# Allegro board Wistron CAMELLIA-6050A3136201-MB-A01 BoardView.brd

Outline 288.7 x 124 mm; copper layers: TOP, L2, L3, L4, L5, L6, L7, BOTTOM. Coordinates in mm from the lower left corner of the outline.

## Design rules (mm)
constraint set DEFAULT: min track width 0.102
net group ALS_LOW_LIGHT_EC: nets ALS_LOW_LIGHT_EC ALS_LOW_LIGHT_PCH
net group AUDIO_CBN: nets AUDIO_CBN AUDIO_CBP
net group AUDIO_DMIC_CLK: nets AUDIO_DMIC_CLK UNNAMED_76_CSC0201_I56_A
net group BATLOW#_N: nets BATLOW# BATLOW#_N
net group BT_OFF: nets BT_OFF BT_OFF_R
net group CAMERA_WP#: nets CAMERA_WP# CAMERA_WP#_EC
net group CCG5_I2C_EC_R_INT#: nets CCG5_I2C_EC_INT# CCG5_I2C_EC_R_INT#
net group CCG5_I2C_EC_R_SCL: nets CCG5_I2C_EC_R_SCL CCG5_I2C_EC_SCL
net group CCG5_I2C_EC_R_SDA: nets CCG5_I2C_EC_R_SDA CCG5_I2C_EC_SDA
net group CCG5_PD_ADP_DIS1#: nets CCG5_PD_ADP_DIS1# CCG5_PD_ADP_DIS1#_R
net group CCG5_PD_ADP_DIS2#: nets CCG5_PD_ADP_DIS2# CCG5_PD_ADP_DIS2#_R
net group CFG<0>: nets CFG<0> XDP_CFG<0>
net group CFG<3>: nets CFG<3> XDP_CFG<3>
net group CL_DATA: nets CL_DATA1 CL_RST#1
net group CLICK_PS2_CLK: nets CLICK_PS2_CLK CLICK_PS2_CLK_R
net group CLICKPAD_INT#: nets CLICKPAD_INT# PCH_CLICKPAD_INT#
net group CLK_PCIE0_D: nets CLK_PCIE0_DN CLK_PCIE0_DP
net group CLK_PCIE_XDP_D: nets CLK_PCIE_XDP_DN CLK_PCIE_XDP_DP
net group CLKIN_XTAL: nets CLKIN_XTAL CLKIN_XTAL_R
net group CLKREQ#_WLAN: nets CLKREQ#_WLAN CLKREQ_WLAN_R_N
net group CN1951_PEDET: nets CN1951_PEDET MSATA_DET
net group CNV_BRI_DT: nets CNV_BRI_DT CNV_BRI_DT_R
net group CNV_BRI_RSP: nets CNV_BRI_RSP CNV_BRI_RSP_R
net group CNV_CLKREQ: nets CNV_CLKREQ CNV_CLKREQ_C
net group CNV_RF_RESET#: nets CNV_RF_RESET# RF_RESET#_C
net group CNV_RGI_DT: nets CNV_RGI_DT CNV_RGI_DT_R
net group CNV_RGI_RSP: nets CNV_RGI_RSP CNV_RGI_RSP_R
net group CPU_C10_GATE#: nets CPU_C10_GATE# VCCIO_LP#
net group DDR_PG_CTRL: nets DDR_PG_CTRL DDR_PG_CTRL_R
net group DDR_WR_C_VREF01: nets DDR_WR_C_VREF01 DDR_WR_VREF01
net group DDR_WR_C_VREF02: nets DDR_WR_C_VREF02 DDR_WR_VREF02
net group DMIC_CLK0: nets DMIC_CLK0 DMIC_R_CLK0
net group DMIC_CLK1: nets DMIC_CLK1 DMIC_R_CLK1
net group DMIC_DATA: nets DMIC_DATA0_PP DMIC_DATA1_PP
net group DPWROK: nets DPWROK DSW_PWROK
net group E-DCLK_PCIE3_U4555_CN1300: nets CLK_PCIE3_DN CLK_PCIE3_DP
net group E-DCLK_PCIE5_U4555_U2700: nets CLK_PCIE5_DN CLK_PCIE5_DP
net group E-DMIC0_CN600_MIC600: nets DMIC_CLK0_DB DMIC_DATA0_DB
net group E-PCIE3_U4555_CN1400: nets CLK_PCIE1_DN CLK_PCIE1_DP
net group E-USB2_P1_CN2400: nets USB_P1_DN USB_P1_DP
net group E-USB2_P4_CN3601: nets USB_P3_DN USB_P3_DP
net group E-USB2_P7_CN1300: nets USB_P7_DN USB_P7_DP
net group EC_GPIO67: nets EC_GPIO67 PCH_SLP_S0IX#
net group EMMC_CLK: nets EMMC_CLK EMMC_CLK_IC
net group EMMC_CMD: nets EMMC_CMD EMMC_CMD_IC
net group EMMC_DATA_0: nets EMMC_DATA_0 EMMC_DATA_0_IC
net group EMMC_DATA_1: nets EMMC_DATA_1 EMMC_DATA_1_IC
net group EMMC_DATA_2: nets EMMC_DATA_2 EMMC_DATA_2_IC
net group EMMC_DATA_3: nets EMMC_DATA_3 EMMC_DATA_3_IC
net group EMMC_DATA_4: nets EMMC_DATA_4 EMMC_DATA_4_IC
net group EMMC_DATA_5: nets EMMC_DATA_5 EMMC_DATA_5_IC
net group EMMC_DATA_6: nets EMMC_DATA_6 EMMC_DATA_6_IC
net group EMMC_DATA_7: nets EMMC_DATA_7 EMMC_DATA_7_IC
net group EMMC_RCLK: nets EMMC_RCLK EMMC_RCLK_IC
net group EN_1V05A: nets EN_1V05A VCC_PRIM_PG
net group ESPI_CLK: nets ESPI_CLK LPC_ESPI_CLK
net group ESPI_LPC#: nets ESPI_LPC# TBT_TMU_CLK_OUT
net group EXT_MIC_JACK_DB: nets EXT_MIC_JACK_DB EXT_MIC_JACK_R_DB
net group FAN1_PWM_EC: nets FAN1_PWM FAN1_PWM_EC
net group FAN1_PWM_Q: nets FAN1_PWM_Q FAN1_PWM_Q_R
net group FN_KEY_LED#: nets FN_KEY_LED# FN_KEY_LED#_R
net group H_PECI: nets H_PECI H_PECI_R
net group H_TCK: nets H_TCK JTAGK_TCK
net group H_TDI: nets H_TDI PCH_TDI
net group H_TDO: nets H_TDO PCH_TDO
net group H_TMS: nets H_TMS PCH_TMS
net group H_TRST#: nets H_TRST# XDP_TRST#
net group HDA_BCLK: nets HDA_BCLK HDA_BCLK_PCH
net group HDA_RST#: nets HDA_RST# HDA_RST#_PCH
net group HDA_SDI0: nets HDA_SDI0 HDA_SDI0_R
net group HDA_SDO_R: nets HDA_SDO_Q HDA_SDO_R
net group HDA_SYNC: nets HDA_SYNC HDA_SYNC_PCH
net group HP_VERF_L: nets EXT_MIC_JACK HP_VERF_L
net group ILIM_SEL_PD: nets ILIM_SEL ILIM_SEL_PD
net group INTRUDER#: nets INTRUDER# INTRUDER#_PCH
net group IOT_I2C_EC_SDA: nets IOT_I2C_EC_SDA IOT_I2C_WWAN_SDA
net group IOT_I2C_WWAN_INT#: nets IOT_I2C_EC_INT# IOT_I2C_WWAN_INT#
net group IOT_I2C_WWAN_SCL: nets IOT_I2C_EC_SCL IOT_I2C_WWAN_SCL
net group JD1: nets HPOUT_DET JD1
net group ON_OFF#1: nets ON_OFF#1 SR1#
net group P3V3S_KBL_EN#: nets P3V3S_KBL_EN# P3V3S_KBL_EN#_RC
net group P5V0S_EN#: nets P5V0S_EN# P5V0S_EN#_R
net group PCH_CIO_PLUG_EVENT: nets PCH_CIO_PLUG_EVENT TBT_CIO_PLUG_EVENT
net group PCH_PWROK: nets PCH_PWROK VCCIO_PG
net group PCIE_RCOMPN: nets PCIE_RCOMPN PCIE_RCOMPP
net group PCIE_RX14_D: nets PCIE_RX14_DN PCIE_RX14_DP
net group PCIE_RX16_D: nets PCIE_RX16_DN PCIE_RX16_DP
net group PLAY_MUTE_LED_CNTR: nets PLAY_MUTE_LED_CNTR PLAY_MUTE_LED_CNTR_R
net group PLT_ID2: nets PLT_ID2 PLT_ID2_PCH
net group PM_SLP_A#: nets PM_SLP_A# PM_SLP_A#_COMPARE
net group PP_DETECT#: nets PP_DETECT# PP_DETECT#_R
net group PRC: nets SLP_S3_5R SLP_S5#_3R
net group PRIVACY_LED#: nets PRIVACY_LED# PRIVACY_LED#_R
net group PVCCSTG_EN: nets PVCCSTG_EN VCCPLL_OC_Q_EN
net group PVT_MISO2: nets PVT_MISO2 PVT_MISO2_EC
net group PVT_MISO3: nets PVT_MISO3 PVT_MISO3_EC
net group PVT_MISO_EC: nets PVT_MISO PVT_MISO_EC
net group PVT_MOSI: nets PVT_MOSI PVT_MOSI_EC
net group PVT_SCLK: nets PVT_SCLK PVT_SCLK_EC
net group RBIAS: nets RBIAS RSENSE
net group RECORD_MUTE_LED_CNTRL: nets RECORD_MUTE_LED_CNTRL RECORD_MUTE_LED_CNTRL_R
net group RTD3_CIO_PWR_EN: nets RTD3_CIO_PWR_EN RTD3_CIO_PWR_EN_BUF
net group SCAN_3S_IN: nets SCAN_3S_IN<4> SCAN_3S_IN<7>
net group SCL_BAT_CHG: nets SCL_BAT_CHG SCL_BAT_R_CHG
net group SCL_P: nets SCL_P UNNAMED_20_MP2949GQKLFZ_I283__1
net group SDA_BAT_CHG: nets SDA_BAT_CHG SDA_BAT_R_CHG
net group SDA_P: nets SDA_P UNNAMED_20_MP2949GQKLFZ_I283_SD
net group SDDR_VREF: nets P0V6S_DIMM0_VREF_CA P0V6S_DIMM1_VREF_CA
net group SPI_DATA: nets PCH_SML1DATA SPI_SI_FLH_R
net group SPI_TPM_CS#_R: nets SPI_TPM_CS# SPI_TPM_CS#_R
net group TBT_CLK: nets TBT_EE_CLK TBT_TCK
net group TBT_USB_FORCE_PWR: nets RTD3_USB_PWR_EN TBT_USB_FORCE_PWR
net group TBTA_FO: nets TBTA_FO TBTA_FO_R
net group TBTA_HPD_R: nets PCH_LAN_SMCLK TBTA_HPD_R
net group TBTB_FO: nets TBTB_FO TBTB_FO_R
net group TOUCH_PWR_EN#: nets TOUCH_PWR_EN# TOUCH_PWR_EN#_RC
net group TPM_PLT_RST#_RC: nets TPM_PLT_RST#_RC UNNAMED_65_NMOS2D2SDIODE_I879_3
net group UART: nets UART0_RXD UART0_TXD
net group UIM_CD: nets UIM_CD UIM_CD#
net group UNNAMED_7_CSC0402_I34_A: nets UNNAMED_7_CSC0402_I34_A UNNAMED_7_CSC0402_I43_A
net group UNNAMED_7_CSC0402_I81_B: nets UNNAMED_7_CSC0402_I81_B UNNAMED_7_CSC0402_I84_B
net group UNNAMED_7_LBSS84LT1G_I27_G: nets UNNAMED_7_LBSS84LT1G_I27_G UNNAMED_7_NMOSC_I234_D
net group USB30_RX1_RE_D_DB: nets USB30_RX1_RE_DN_DB USB30_RX1_RE_DP_DB
net group USB30_RX2_RE_D_DB: nets USB30_RX2_RE_DN_DB USB30_RX2_RE_DP_DB
net group USB_P4_D: nets USB_P4_DN USB_P4_DP
net group VCC1_RST#: nets VCC1_R_RST# VCC1_RST#
net group VCCIO_VSSSENSE: nets UNNAMED_18_CSC0402_I59_B VCCIO_VSSSENSE
net group VCCPLL_OC_EN: nets VCCPLL_OC_EN VCCPLL_OC_XDP_EN
net group VCCSA_SENSE: nets VCCSA_VCCSENSE VCCSA_VSSSENSE
net group VCCSENSE: nets VCCSENSE VOSENA
net group VGT_VCCSENSE: nets VGT_VCCSENSE VOSENB
net group VGT_VSSSENSE: nets VGT_VSSSENSE VORTNB
net group VORTNA: nets VORTNA VSSSENSE
net group WWAN_WAKE#_R: nets WWAN_WAKE# WWAN_WAKE#_R
net group XDP_PRSNT#: nets XDP_PRSNT# XDP_PRSNT#_R
net group XTAL24_IN: nets XTAL24_IN XTAL24_OUT
net group XTAL24_IN_PCH: nets XTAL24_IN_PCH XTAL24_OUT_PCH
net group 1V05A_PG: nets 1V05A_PG 5V_PG COMPARE_R_RSMRST_PG COMPARE_RSMRST_PG EC_RSMRST_PG RSMRST_PG
net group 8051_RX_CAPS_LED#: nets 8051_RX_CAPS_LED# CAPS_LED# CAPS_LED#_R
net group 8051_TX_LED_PWRSTBY#: nets 8051_TX_LED_PWRSTBY# LED_PWRSTBY# LED_PWRSTBY#_CNTR LED_PWRSTBY#_CNTR_R
net group ABMON: nets ABMON EC_ADC1 UNNAMED_7_ISL9241HRTZ_I169_29
net group ASY: nets THERMTRIP_CPU#
net group AUDIO-B: nets A_LINEINL A_LINEINR HP_OUT_L1 HP_OUT_R1
net group AUDIO_AVDD1: nets AUDIO_AVDD1 AUDIO_AVDD1_R PCBEEP PCH_SPKR PCH_SPKR_R PCH_SPKR_R_R
net group AUDIO_PDB: nets A_SD# AUDIO_PDB SPKR_EN_AB SPKR_EN_AB_AUDIO
net group BARREL_ADP_DET: nets BARREL_ADP_DET BARREL_ADP_DET_EC UNNAMED_7_PNPA_I117_B UNNAMED_7_RSC0402_I114_B
net group BKLT_EN: nets BKLT_EN EDP_BKLT_EN TOUCH_SWITCH_EN
net group BUF_PLT_RST#: nets BUF_PLT_RST# TD_IREF TD_IREF_R WLAN_PLT_RST#
net group CCG5_MOD_ID1: nets CCG5_MOD_ID1 CCG5_MOD_ID2 CCG5_PVCC_PD CCG5_SWD_CLK CCG5_SWD_XRES CCG5_VBUS_P_CTRL_P1 CCG5_VBUS_P_CTRL_P2
net group CCG5_SBU1_A_DP_DP: nets CCG5_SBU2_A_DN
net group CCG5_SBU1_B_DP_DP: nets CCG5_SBU2_B_DN
net group CCG5_VBUS_CSN1: nets CCG5_VBUS_CSN1_R
net group CCG5_VBUS_CSN2: nets CCG5_VBUS_CSN2_R
net group CFG1_15: nets CFG<1> CFG<2> CFG<4> CFG<5> CFG<6> CFG<7> CFG<8> CFG<9> CFG<10> CFG<11> CFG<12> CFG<13> CFG<14> CFG<15> CFG<16> CFG<17> CFG<18> CFG<19>
net group CL_CLK: nets CL_CLK1
net group CLICKPAD_DISABLE#: nets CLICKPAD_DISABLE# CLICKPAD_DISABLE#_R FPR_LID_SW#_3
net group CLKREQ: nets CLKREQ#_DGPU CLKREQ#_SSD CLKREQ#_WWAN
net group COMPARE_PWR_GOOD_3: nets COMPARE_PWR_GOOD_3 COMPARE_R_PWR_GOOD_3 EN_VCCIO PWR_GOOD_3
net group CPU_PROCHOT#: nets CPU_PROCHOT# CPU_PROCHOT#_R OCP_CHG# UNNAMED_9_NMOSC_I61_D UNNAMED_20_MP2949GQKLFZ_I283_VR
net group CSON: nets CSON CSOP UNNAMED_7_RSC0402_I221_B UNNAMED_7_RSC12064PIN_I238_3
net group DDR_VTT_PG_CTRL: nets DDR_VTT_PG_CTRL DDR_VTT_PG_CTRL_R EN_VTT
net group DEFAULT-PWR: nets PVCORE_PG VRAVR_ON VRPPM_SLP_S0_N
net group DMIC_DATA0: nets DMIC_DATA0 DMIC_DATA0_PCH DMIC_R_DATA0
net group DMIC_DATA1: nets DMIC_DATA1 DMIC_DATA1_PCH DMIC_R_DATA1
net group DP-DDC-CLK: nets DPB_DDCCLK DPB_HDMI_DDC_CLK DPC_DDCCLK
net group DP-DDC-DATA: nets DPB_DDCDATA DPB_HDMI_DDC_DATA DPC_DDCDATA
net group DPB_TR_AUX_DN: nets DPB_TR_AUX_C_DN
net group DPB_TR_AUX_DP: nets DPB_TR_AUX_C_DP
net group E-DDR_RESET_CN4125: nets DDR4_DRAMRST#
net group E-EDP_RCOMP: nets DISP_RCOMP
net group E-LPC_CLK_U4555_U300: nets LPC_ESPI_RESET#
net group E-PCIE14_U4555_CN1951: nets PCIE_RX9_DN PCIE_RX9_DP PCIE_RX10_DN PCIE_RX10_DP PCIE_RX11_DN PCIE_RX11_DP PCIE_RX12_DN PCIE_RX12_DP
net group E-RTC_RST: nets RTCRST#
net group E-SDDR-A-CLK: nets M_CLK_DDR0_DP M_CLK_DDR1_DN M_CLK_DDR1_DP
net group E-SDDR-A-CMD: nets M_A_A_0 M_A_A_1 M_A_A_2 M_A_A_3 M_A_A_4 M_A_A_5 M_A_A_6 M_A_A_7 M_A_A_8 M_A_A_9 M_A_A_10 M_A_A_11 M_A_A_12 M_A_A_13 M_A_A_14 M_A_A_15 M_A_A_16 M_A_ACT# M_A_BG0 M_A_BG1 M_A_BS0 M_A_BS1 M_A_PAR
net group E-SDDR-A-CMD-CLK: nets M_CLK_DDR0_DN
net group E-SDDR-A-CTRL: nets M_CKE0 M_CKE1 M_CS#0 M_CS#1 M_ODT0 M_ODT1
net group E-SDDR-A-DQS0: nets M_A_DQ<0> M_A_DQ<1> M_A_DQ<2> M_A_DQ<3> M_A_DQ<4> M_A_DQ<5> M_A_DQ<6> M_A_DQ<7>
net group E-SDDR-A-DQS1: nets M_A_DQ<8> M_A_DQ<9> M_A_DQ<10> M_A_DQ<11> M_A_DQ<12> M_A_DQ<13> M_A_DQ<14> M_A_DQ<15>
net group E-SDDR-A-DQS2: nets M_A_DQ<16> M_A_DQ<17> M_A_DQ<18> M_A_DQ<19> M_A_DQ<20> M_A_DQ<21> M_A_DQ<22> M_A_DQ<23>
net group E-SDDR-A-DQS3: nets M_A_DQ<24> M_A_DQ<25> M_A_DQ<26> M_A_DQ<27> M_A_DQ<28> M_A_DQ<29> M_A_DQ<30> M_A_DQ<31>
net group E-SDDR-A-DQS4: nets M_A_DQ<32> M_A_DQ<33> M_A_DQ<34> M_A_DQ<35> M_A_DQ<36> M_A_DQ<37> M_A_DQ<38> M_A_DQ<39>
net group E-SDDR-A-DQS5: nets M_A_DQ<40> M_A_DQ<41> M_A_DQ<42> M_A_DQ<43> M_A_DQ<44> M_A_DQ<45> M_A_DQ<46> M_A_DQ<47>
net group E-SDDR-A-DQS6: nets M_A_DQ<48> M_A_DQ<49> M_A_DQ<50> M_A_DQ<51> M_A_DQ<52> M_A_DQ<53> M_A_DQ<54> M_A_DQ<55>
net group E-SDDR-A-DQS7: nets M_A_DQ<56> M_A_DQ<57> M_A_DQ<58> M_A_DQ<59> M_A_DQ<60> M_A_DQ<61> M_A_DQ<62> M_A_DQ<63>
net group E-SDDR-A-DQS-CLK: nets M_A_DQS0_DN M_A_DQS0_DP M_A_DQS1_DN M_A_DQS1_DP M_A_DQS2_DN M_A_DQS2_DP M_A_DQS3_DN M_A_DQS3_DP M_A_DQS4_DN M_A_DQS4_DP M_A_DQS5_DN M_A_DQS5_DP M_A_DQS6_DN M_A_DQS6_DP M_A_DQS7_DN M_A_DQS7_DP
net group E-SDDR-B-CLK: nets M_CLK_DDR2_DP M_CLK_DDR3_DN M_CLK_DDR3_DP
net group E-SDDR-B-CMD: nets M_B_A_0 M_B_A_1 M_B_A_2 M_B_A_3 M_B_A_4 M_B_A_5 M_B_A_6 M_B_A_7 M_B_A_8 M_B_A_9 M_B_A_10 M_B_A_11 M_B_A_12 M_B_A_13 M_B_A_14 M_B_A_15 M_B_A_16 M_B_ACT# M_B_BG0 M_B_BG1 M_B_BS0 M_B_BS1 M_B_PAR
net group E-SDDR-B-CMD-CLK: nets M_CLK_DDR2_DN
net group E-SDDR-B-CTRL: nets M_CKE2 M_CKE3 M_CS#2 M_CS#3 M_ODT2 M_ODT3
net group E-SDDR-B-DQS0: nets M_B_DQ<0> M_B_DQ<1> M_B_DQ<2> M_B_DQ<3> M_B_DQ<4> M_B_DQ<5> M_B_DQ<6> M_B_DQ<7>
net group E-SDDR-B-DQS1: nets M_B_DQ<8> M_B_DQ<9> M_B_DQ<10> M_B_DQ<11> M_B_DQ<12> M_B_DQ<13> M_B_DQ<14> M_B_DQ<15>
net group E-SDDR-B-DQS2: nets M_B_DQ<16> M_B_DQ<17> M_B_DQ<18> M_B_DQ<19> M_B_DQ<20> M_B_DQ<21> M_B_DQ<22> M_B_DQ<23>
net group E-SDDR-B-DQS3: nets M_B_DQ<24> M_B_DQ<25> M_B_DQ<26> M_B_DQ<27> M_B_DQ<28> M_B_DQ<29> M_B_DQ<30> M_B_DQ<31>
net group E-SDDR-B-DQS4: nets M_B_DQ<32> M_B_DQ<33> M_B_DQ<34> M_B_DQ<35> M_B_DQ<36> M_B_DQ<37> M_B_DQ<38> M_B_DQ<39>
net group E-SDDR-B-DQS5: nets M_B_DQ<40> M_B_DQ<41> M_B_DQ<42> M_B_DQ<43> M_B_DQ<44> M_B_DQ<45> M_B_DQ<46> M_B_DQ<47>
net group E-SDDR-B-DQS6: nets M_B_DQ<48> M_B_DQ<49> M_B_DQ<50> M_B_DQ<51> M_B_DQ<52> M_B_DQ<53> M_B_DQ<54> M_B_DQ<55>
net group E-SDDR-B-DQS7: nets M_B_DQ<56> M_B_DQ<57> M_B_DQ<58> M_B_DQ<59> M_B_DQ<60> M_B_DQ<61> M_B_DQ<62> M_B_DQ<63>
net group E-SDDR-B-DQS-CLK: nets M_B_DQS0_DN M_B_DQS0_DP M_B_DQS1_DN M_B_DQS1_DP M_B_DQS2_DN M_B_DQS2_DP M_B_DQS3_DN M_B_DQS3_DP M_B_DQS4_DN M_B_DQS4_DP M_B_DQS5_DN M_B_DQS5_DP M_B_DQS6_DN M_B_DQS6_DP M_B_DQS7_DN M_B_DQS7_DP
net group E-USB2_P5_U2600: nets USB_P5_DN USB_P5_DP USB_P6_DN USB_P6_DP
net group E-USB3_P1_CN2400: nets USB30_RX1_DN USB30_RX1_DP USB30_TX1_DN USB30_TX1_DP
net group E-USB3_P2_CN2500: nets USB30_RX2_DN USB30_RX2_DP USB30_TX2_DN USB30_TX2_DP
net group E-XCLK_BIASREF: nets XCLK_BIASREF
net group EC_ADC0: nets EC_ADC0 IMVP_PSYS UNNAMED_20_CSC0402_I154_A
net group EC_ADC2: nets EC_ADC2 LIMIT_SIGNAL OCP_ID_ADC2 UNNAMED_9_CSC0402_I39_A UNNAMED_9_NMOSC_I60_D UNNAMED_9_NPND_I37_B UNNAMED_9_RSC0402_I44_A
net group EDP_PWM_OUT_RC: nets EDP_PWM_OUT EDP_PWM_OUT_R EDP_PWM_OUT_RC PWM_EC_IN
net group EDP_TX0_C_R_DN: nets EDP_TX0_DN
net group EDP_TX0_C_R_DP: nets EDP_TX0_DP
net group EDP_TX1_C_R_DN: nets EDP_TX1_DN
net group EDP_TX1_C_R_DP: nets EDP_TX1_DP
net group EDP_TX2_C_R_DN: nets EDP_TX2_DN
net group EDP_TX2_C_R_DP: nets EDP_TX2_DP
net group EDP_TX3_C_R_DN: nets EDP_TX3_DN
net group EDP_TX3_C_R_DP: nets EDP_TX3_DP
net group EMMC_RCOMP: nets EMMC_RCOMP
net group EN_1V8: nets EN_1V8 KBC_PWR_ON P3V3A_EN SLP_S4#_3R SLP_S4#_3R_KBC SLP_S4#_3R_PCH SLP_S4#_3R_R
net group ESPI_0: nets ESPI_0 LPC_ESPI_<0> LPC_ESPI_R_<0>
net group ESPI_1: nets ESPI_1 LPC_ESPI_<1> LPC_ESPI_R_<1>
net group ESPI_2: nets ESPI_2 LPC_ESPI_<2> LPC_ESPI_R_<2>
net group ESPI_3: nets ESPI_3 LPC_ESPI_<3> LPC_ESPI_R_<3>
net group GND: nets AGND_AUDIO AGND_KBC AGND_USB DGND DGND_ALS DGND_DMIC_FRONT GND_ALS WLAN_GND
net group HDAA: nets HDA_SDO
net group HP_OUT_R_L1_DB: nets HP_OUT_L1_DB HP_OUT_R_L1_DB HP_OUT_R_R_L1_DB
net group HP_OUT_R_R1_DB: nets HP_OUT_R1_DB HP_OUT_R_R1_DB HP_OUT_R_R_R1_DB
net group I2C_CLK_1M: nets 1ALS_HUB_SMCLK_DB ALS_HUB_SMCLK_DB ALS_PL_SMCLK_DB AUDIO_I2C_SCL I2C_ALS_SMCLK I2C_TOUCH_CLK I2C_TOUCH_Q_CLK PCH_3A_SMCLK PCH_3S_SMCLK PCH_I2C3_3S_SCL PCH_I2C3_SCL PCH_KBC_SMCLK SSD_SUSCLK TBT_I2C_SCL WLAN_I2CCLK
net group I2C_CLK_100M: nets ISH_I2C0_SCL
net group I2C_DATA: nets 1ALS_HUB_SMDATA_DB ALS_HUB_SMDATA_DB ALS_PL_SMDATA_DB AUDIO_I2C_SDA I2C_ALS_SMDATA I2C_TOUCH_DAT I2C_TOUCH_Q_DAT ISH_I2C0_SDA PCH_3A_SMDATA PCH_3S_SMDATA PCH_I2C3_3S_SDA PCH_I2C3_SDA PCH_KBC_SMDATA TBT_I2C_SDA WLAN_I2DATA
net group I_SET: nets I_SET UNNAMED_7_CSC0402_I218_A UNNAMED_7_CSC0402_I218_B UNNAMED_7_ISL9241HRTZ_I169_14 UNNAMED_7_ISL9241HRTZ_I169_15 UNNAMED_7_RSC0402_I224_B UNNAMED_7_RSC12064PIN_I16_4
net group KSCAN_3S_IN: nets KSCAN_3S_IN<0> KSCAN_3S_IN<1> KSCAN_3S_IN<2> KSCAN_3S_IN<3> KSCAN_3S_IN<4> KSCAN_3S_IN<5> KSCAN_3S_IN<6> KSCAN_3S_IN<8> KSCAN_3S_IN<9> KSCAN_3S_IN<10> KSCAN_3S_IN<11> KSCAN_3S_IN<12> KSCAN_3S_IN<13> KSCAN_3S_IN<14>
net group LFRAM#_ESPI_CS#: nets LFRAM#_ESPI_CS#_R
net group LPC_CLK: nets PCH_SML1CLK
net group LPC_DATA: nets ESPI_ALERT#
net group MAIN_BAT_DET#: nets MAIN_BAT_DET# MAIN_BAT_DET#_BAT MAIN_BAT_DET#_EC
net group ON_OFF#1_Q: nets ON_OFF#1_Q ON_OFF#1_Q_XDP PWR_BTN_OUT# PWRBTN#
net group OTHER_CLK_S5: nets THERM_CLK
net group OTHER_CLK_S15: nets PCH_TCK
net group OTHER_DATA: nets CCG5_SWD_IO PVT_CS# THERM_DATA
net group PCH_WAKE#: nets PCH_WAKE# PCH_WAKE#_R PCH_WAKE#_WWAN TBT_PCIE_WAKE_N TBT_WAKE#_PCH WLAN_WAKE#
net group PLAY_MUTE_LED_AUDIO: nets PLAY_MUTE_LED PLAY_MUTE_LED_AUDIO PLAY_MUTE_LED_PCH
net group PLT_RST#_KBC: nets PLT_RST# PLT_RST#_KBC PLT_RST#_PCH
net group PP_DETECT: nets PP_DETECT PP_HVA PP_HVA_R PP_SELECT
net group PVCCSFR_PWRGD_R: nets PVCCSFR_PWRGD_R PVCCSFR_PWRGD_R_R VCCST_PWRGD
net group PWM_EC_OUT: nets EDP_PWM_R EDP_PWM_R_OUT PWM_EC_OUT PWM_EC_OUT_R
net group PWR-W10: nets AUDIO_AVDD DCIN DIS_P1V8S DIS_P3V3S_LCDVDD DIS_P3V3S_TOUCH_VCC DIS_P5V0S EC_AVCC EC_AVCC_R EC_VCC EC_VSPI P0V6S P0V9_LC P0V9_PCIE P1V2 P1V05A P1V5S P1V8A_EMMC P1V8S P1V8S_AUDIO P2V5 P2V8S_FRONT_DMIC P3V3_ANA P3V3_ANA_PCIE P3V3_ANA_USB2 P3V3_LC P3V3_RTC P3V3_SVR P3V3_SX P3V3A_EMMC P3V3A_PRIME P3V3A_PRIME_EN P3V3A_SS2 P3V3AL_KBC P3V3AL_RTC_BAT P3V3AL_RTC_BAT_D4750 P3V3DS_CCG5 P3V3DS_U5002_PIN3 P3V3DS_WLAN P3V3DS_WWAN P3V3S P3V3S_ALS P3V3S_ALS_HUB_DB P3V3S_AUDIO P3V3S_CAMERA_ALS P3V3S_LCDVDD P3V3S_R_LCDVDD P3V3S_SS1 P3V3S_SSD P3V3S_TOUCH_F P3V3S_TOUCH_VCC P3V3S_USB P3V3S_USB_DB P5V0A_USB P5V0A_USB1 P5V0A_USB_CHARGE P5V0A_USB_CHARGE_DB P5V0A_USB_DB P5V0DS P5V0DS_RC P5V0S P5V0S_AUDIO_AVDD P5V0S_HDMI P5V0S_IR_LED P5V0S_KBL P5V0S_RC P5V0S_SM PV_VBUS_CNTR_1 PV_VBUS_CNTR_2 PVADP PVBAT_CPU1 PVBAT_CPU2 PVBAT_CPU3 PVBAT_GT PVBAT_LCM PVBAT_SA PVCC_PRIM PVCCGT PVCCIO PVCCSA PVCCSFR PVCCSTG PVCORE PVPACK PVSYS PWRSW_P3V3A PWRSW_P3V3S SPI_TPM_VCC VCC0V9_LVR_OUT
net group PWR-W20: nets UIM_PWR
net group PWR-W40: nets P1V8A P3V3A P3V3A_Q_WLAN
net group PWR-W120: nets VADPBL
net group PWR_PROPERITY_1: nets D_COVER_OPEN
net group RECORD_MUTE_LED_AUDIO: nets RECORD_MUTE_LED RECORD_MUTE_LED_AUDIO RECORD_MUTE_LED_PCH
net group RSMRST#_EC: nets RSMRST# RSMRST#_EC VCCST_PWRGD_XDP
net group SCAN_3S_OUT: nets SCAN_3S_OUT<4> SCAN_3S_OUT<5> SCAN_3S_OUT<6> SCAN_3S_OUT<8> SCAN_3S_OUT<9> SCAN_3S_OUT<10> SCAN_3S_OUT<11>
net group SDDR_A_CAC: nets M_A_ALERT#
net group SDDR_B_CAC: nets M_B_ALERT#
net group SDDR_RCOMP: nets DDR_RCOMP_0 DDR_RCOMP_1 DDR_RCOMP_2
net group SLP_S3#_3R_N: nets EN_1V5 P3V3S_EN SLP_S3#_3R SLP_S3#_3R_COMPARE SLP_S3#_3R_KBC SLP_S3#_3R_N SLP_S3#_3R_PCH SLP_S3#_3R_RC SLP_S3#_XDP_PRSNT
net group SMB_CLK: nets NFC_CLICK_3S_SMCLK
net group SMB_DATA: nets NFC_CLICK_3S_SMDATA
net group SPI_CLK_FLH: nets SPI_CLK_EC SPI_CLK_EC_R SPI_CLK_FLH SPI_CLK_PCH SPI_CLK_PCH_R
net group SPI_CS0#_EC_R: nets SPI_CS0#_EC SPI_CS0#_EC_R SPI_CS0#_FLH SPI_CS0#_PCH SPI_CS0#_PCH_R
net group SPI_SI_EC: nets SPI_SI_EC SPI_SI_EC_R SPI_SI_FLH SPI_SI_PCH SPI_SI_PCH_R
net group SPI_SO2_EC_R: nets SPI_SO2_EC_R SPI_SO2_FLH SPI_SO2_PCH SPI_SO2_PCH_R XDP_PRSNT#_D
net group SPI_SO3_EC_R: nets SPI_SO3_EC_R SPI_SO3_FLH SPI_SO3_PCH SPI_SO3_PCH_R
net group SPI_SO_FLH: nets SPI_SO_EC SPI_SO_EC_R SPI_SO_FLH SPI_SO_PCH SPI_SO_PCH_R
net group SPK_OUT_L_DN: nets SPK_OUT_L_DN
net group SPK_OUT_L_DP: nets SPK_OUT_L_DP
net group SUSCLK32_KBC: nets SUSCLK32_KBC SUSCLK32_PCH SUSCLK32_PCH_WLAN
net group SVID: nets VR_SVID_ALERT# VR_SVID_CLK VR_SVID_DATA
net group TBT_DATA: nets TBT_EE_CS_N TBT_EE_DI TBT_EE_DO TBT_EE_WP_N TBT_TDI TBT_TDO TBT_TMS
net group TBT_XTAL_25_IN: nets TBT_XTAL_25_IN TBT_XTAL_25_OUT TBT_XTAL_25_R_IN TBT_XTAL_25_R_OUT
net group TBTB_HPD_R: nets PCH_LAN_SMDATA TBTB_HPD TBTB_HPD_R
net group UIM_CLK: nets UIM_CLK
net group UIM_DATA: nets UIM_DATA UIM_RST UIM_VPP
net group UNNAMED_7_LBSS84LT1G_I208_G: nets UNNAMED_7_LBSS84LT1G_I208_G UNNAMED_7_LBSS84LT1G_I208_S UNNAMED_7_NMOSC_I202_D
net group UNNAMED_19_CSC0402_I55_A: nets UNNAMED_19_CSC0402_I55_A UNNAMED_19_CSC0402_I55_B UNNAMED_19_NB692GD_I42_12
net group USB_CHARGER_STATUS#: nets USB_CHARGER_STATUS# USB_CHARGER_STATUS#_PD USB_CHARGER_STATUS#_R
net group USB_RBAIS: nets USB2_COMP
net group V_ADP_ADC4: nets EC_ADC4 UNNAMED_9_CSC0402_I17_A V_ADP_ADC4
net group VCCIO_SENSE: nets VCCIO_VCCSENSE
net group VRA: nets NFC_3V3 NFC_3V3_R VRA1V5_FB VRA1V05A_FB VRA1V05A_FF VRA1V05A_ILMT VRA1V05A_SNB VRA1V05A_VOUT VRA1V8A_FB VRA1V8A_FF VRA1V8A_ILMT VRA1V8A_SNB VRA1V8A_VOUT VRA2V5_FB VRA3V3A_SNB VRA3V3A_VCC VRA3V3DS_VOUT VRA5V0_SNB VRA5V0A_FF VRA5V0A_FF_R VRA5V0A_LDO VRA5V0A_OUT VRA5V0A_SNB VRA5V0A_VOUT VRA_1V05A_VCC VRA_1V8A_VCC VRA_5V0A_VCC VRA_VDD18 VRABGATE VRABYPSGATE VRABYPSRC VRACHG_BATGONE VRACHG_SNB1 VRACHG_SNB2 VRACPU_BST1 VRACPU_BST2 VRACPU_BST3 VRACPU_CS1 VRACPU_CS2 VRACPU_CS3 VRACPU_IMON VRACPU_IREF VRACPU_PE VRACPU_PE_EC VRACPU_PWM1 VRACPU_PWM2 VRACPU_PWM3 VRACPU_SNB1 VRACPU_SNB2 VRACPU_SNB3 VRACPU_STB VRACPU_VDD33 VRACPU_VDIFF VRACPU_VFB VRACPU_VFB1 VRACPU_VINSEN VRACPU_VTEMP VRACPU_VTEMP1 VRAGT_BST1 VRAGT_CS1 VRAGT_IMON VRAGT_PWM1 VRAGT_SNB1 VRAGT_VDIFF VRAGT_VFB VRAGT_VFB1 VRAPACK_VBAT VRASA_BST1 VRASA_CS1 VRASA_CSUMC VRASA_IMON VRASA_PWM1 VRASA_SNB1 VRASA_VDIFF VRASA_VFB VRASA_VFB1 VRASA_VORTN VRASA_VOSEN VRAVCC_PRIM_SNB VRAVCCIO_BST VRAVCCIO_BST1 VRAVCCIO_MODE VRAVCCIO_SNB VRAVDD VRAVDDP VRAVDDQ_BST VRAVDDQ_FB VRAVDDQ_MODE VRAVDDQ_OTW# VRAVDDQ_SNB VRAVDDQ_VOUT
net group VRA5V0_EN1: nets EN_3V EN_5V EN_5V_3V EN_USB5V RST1# UNNAMED_11_RSCSHORT_I47_B VRA3V3A_AGND VRA5V0_EN1 VRA5V0_EN2
net group VRA5V0_FF: nets VRA5V0_FF VRA5V0_FF_R VRA5V0_VOUT VRA5V0_VOUT1
net group VRA-S20: nets PVBAT
net group VRB: nets VRB1V05A_BST VRB1V05A_BST1 VRB1V8A_BST VRB1V8A_BST1 VRB3V3A_BST VRB3V3A_BST1 VRB5V0_BST VRB5V0_BST1 VRB5V0A_BST VRB5V0A_BST1 VRB_ADP_SELEC VRB_VDD3 VRB_VDD5 VRBVCC_PRIM_BST VRBVCC_PRIM_BST1
net group VRP: nets COMPARE_VRP3V3A_LDO VRP1V5 VRP1V5_PH VRP1V5_VIN VRP1V05A VRP1V05A_PH VRP1V05A_VIN VRP1V8A VRP1V8A_PH VRP1V8A_VIN VRP2V5 VRP2V5_PH VRP2V5_VIN VRP3V3A VRP3V3A_LDO_RC VRP3V3A_PH VRP3V3A_VIN VRP5V0 VRP5V0_PH VRP5V0_VIN VRP5V0A VRP5V0A_PH VRP5V0A_VIN VRPCHG_BST1 VRPCHG_BST1_R VRPCHG_BST2 VRPCHG_BST2_R VRPCHG_HG1 VRPCHG_HG2 VRPCHG_LG1 VRPCHG_LG2 VRPCHG_PH1 VRPCHG_PH2 VRPCPU_PH1 VRPCPU_PH2 VRPCPU_PH3 VRPGT_PH1 VRPRIM_VIN VRPSA_PH1 VRPVCC_PRIM VRPVCC_PRIM_PH VRPVCCIO VRPVCCIO_PH VRPVCCIO_VIN VRPVDDQ VRPVDDQ_PH VRPVDDQ_VIN VRPVTT VRPVTT_REF
net group WLAN_OFF: nets WLAN_OFF WLAN_OFF_R WLAN_PWR_EN#
nets with their own width: min track width 0.254; nets DGND_USB P3V3A_LDO

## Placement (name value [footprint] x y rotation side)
C100  1uF_6.3V_1  [CSC_060X030X035_2]  240.26 30.88 0 top
C131  0.1uF_6.3V_1  [CSC_060X030X030_2]  244.58 34.39 180 top
C300  0.1uF_6.3V_1  [CSC_060X030X030_2]  50.06 17.72 90 bottom
C301  2200pF_16V_1  [CSC_060X030X033_2]  248.54 40.07 0 top
C302  1uF_6.3V_1  [CSC_060X030X035_2]  236.01 34.25 270 top
C303  0.1uF_6.3V_1  [CSC_060X030X030_2]  231.57 40.48 270 top
C304  2200pF_16V_1  [CSC_060X030X033_2]  247.47 35.85 0 top
C305  1uF_6.3V_1  [CSC_060X030X035_2]  243.07 34.05 180 top
C306  1uF_6.3V_1  [CSC_060X030X035_2]  243.51 33.16 270 top
C307  4.7UF_6.3V_2  [CSC_100X050X065_2]  248.41 41.82 90 top
C308  0.1uF_6.3V_1  [CSC_060X030X030_2]  234.87 49.37 90 top
C309  2200pF_16V_1  [CSC_060X030X033_2]  248.54 40.71 0 top
C310  0.1uF_6.3V_1  [CSC_060X030X030_2]  232.18 40.48 270 top
C311  1uF_6.3V_1  [CSC_060X030X035_2]  248.51 44.79 180 top
C312  0.1uF_6.3V_1  [CSC_060X030X030_2]  248.51 44.19 180 top
C313  0.1uF_6.3V_1  [CSC_060X030X030_2]  248.54 39.44 180 top
C314  0.1uF_6.3V_1  [CSC_060X030X030_2]  235.38 34.25 270 top
C315  0.1uF_6.3V_1  [CSC_060X030X030_2]  244.58 34.99 180 top
C316  0.1uF_6.3V_1  [CSC_060X030X030_2]  219.48 28.26 315 top
C317  0.1uF_6.3V_1  [CSC_060X030X030_2]  245.18 41.57 90 top
C318  4.7UF_6.3V_2  [CSC_100X050X065_2]  248.31 38.65 180 top
C319  2.2UF_6.3V_1  [CSC_060X030X033_2]  235.48 49.37 90 top
C320  2200pF_16V_1  [CSC_060X030X033_2]  247.09 35.19 0 top
C321  0.1uF_6.3V_1  [CSC_060X030X030_2]  223.67 55.64 90 bottom
C322  10uF_6.3V_2  [CSC_100X050X070_2]  229.81 39.9 0 top
C323  1000pF_25V_1  [CSC_060X030X030_2]  111.02 7.81 270 bottom
C324  0.1uF_6.3V_1  [CSC_060X030X030_2]  231.9 43.78 180 top
C325  0.1uF_6.3V_1  [CSC_060X030X030_2]  238.4 48.48 270 top
C326  0.1uF_6.3V_1  [CSC_060X030X030_2]  132.36 3.75 180 bottom
C327  10pF_50V_2  [CSC_100X050X040_2]  231.29 56.33 180 top
C366  0.1uF_6.3V_1  [CSC_060X030X030_2]  229.13 58.23 270 top
C500  2.2UF_6.3V_3  [CSC_160X080X090_2]  25.04 45.25 270 top
C501  2.2UF_6.3V_2  [CSC_100X050X055_2]  18.77 44.54 0 top
C502  0.1uF_6.3V_1  [CSC_060X030X030_2]  27.1 41.44 0 top
C503  10uF_6.3V_2  [CSC_100X050X070_2]  27.3 42.2 0 top
C504  10uF_6.3V_2  [CSC_100X050X070_2]  27.09 39.19 0 top
C505  0.1uF_6.3V_1  [CSC_060X030X030_2]  26.95 39.93 0 top
C506  10uF_6.3V_2  [CSC_100X050X070_2]  21.23 45.68 270 top
C507  4.7UF_6.3V_2  [CSC_100X050X065_2]  17.14 44.59 0 top
C508  10uF_6.3V_2  [CSC_100X050X070_2]  27.05 43.52 0 top
C509  2.2UF_6.3V_3  [CSC_160X080X090_2]  26.36 45.28 90 top
C510  4.7UF_6.3V_2  [CSC_100X050X065_2]  27.15 40.68 0 top
C511  0.1uF_6.3V_1  [CSC_060X030X030_2]  26.97 36.52 0 top
C512  0.1uF_6.3V_1  [CSC_060X030X030_2]  17.21 36.96 270 top
C513  10uF_6.3V_2  [CSC_100X050X070_2]  16.45 36.02 270 top
C514  0.1uF_16V_2  [CSC_100X050X040_2]  12.35 44.79 270 top
C515  100pF_50V_2  [CSC_100X050X040_2]  16.99 45.86 270 top
C516  0.1uF_10V_1  [CSC_060X030X030_2]  17.54 42.19 270 top
C517  10uF_6.3V_2  [CSC_100X050X070_2]  16.78 42.45 270 top
C518  0.1uF_6.3V_1  [CSC_060X030X030_2]  16.02 41.57 90 top
C519  10uF_6.3V_2  [CSC_100X050X070_2]  15.26 41.75 90 top
C520  0.1uF_6.3V_1  [CSC_060X030X030_2]  20.44 36.59 180 top
C521  10uF_6.3V_2  [CSC_100X050X070_2]  23.42 32.83 270 top
C522  0.1uF_6.3V_1  [CSC_060X030X030_2]  15.69 35.73 270 top
C523  10uF_6.3V_2  [CSC_100X050X070_2]  14.82 35.97 270 top
C524  0.1uF_10V_1  [CSC_060X030X030_2]  28.44 44.49 180 top
C525  0.1uF_10V_1  [CSC_060X030X030_2]  4.98 43.37 90 top
C526  10uF_6.3V_2  [CSC_100X050X070_2]  15.54 45.56 180 top
C527  0.1uF_16V_2  [CSC_100X050X040_2]  20.34 45.68 90 top
C640  100pF_50V_1  [CSC_060X030X030_2]  4.16 37.19 180 top
C641  100pF_50V_1  [CSC_060X030X030_2]  4.16 36.58 180 top
C642  100pF_50V_1  [CSC_060X030X030_2]  4.16 39.27 180 top
C643  100pF_50V_1  [CSC_060X030X030_2]  4.16 39.88 180 top
C1000  0.1uF_10V_1  [CSC_060X030X030_2]  235.61 27.9 90 top
C1001  1uF_6.3V_1  [CSC_060X030X035_2]  141.75 9.46 90 top
C1002  0.01UF_25V_1  [CSC_060X030X033_2]  261.67 2.35 270 bottom
C1300  4.7uF_6.3V_3  [CSC_160X080X090_2]  61.24 15.81 180 bottom
C1301  0.1uF_10V_1  [CSC_060X030X030_2]  47.27 25.47 180 bottom
C1302  0.01UF_25V_1  [CSC_060X030X033_2]  60.47 18.61 180 bottom
C1303  10uF_6.3V_3  [CSC_160X080X095_2]  61.24 17.08 180 bottom
C1304  0.1uF_10V_1  [CSC_060X030X030_2]  60.47 18 180 bottom
C1305  0.01UF_25V_1  [CSC_060X030X033_2]  47.27 26.1 180 bottom
C1306  10uF_6.3V_3  [CSC_160X080X095_2]  47.77 24.45 180 bottom
C1307  2.2UF_6.3V_2  [CSC_100X050X055_2]  48.79 23 0 bottom
C1309  0.047uF_6.3V_1  [CSC_060X030X030_2]  50.59 34.89 270 bottom
C1400  10uF_6.3V_3  [CSC_160X080X095_2]  218.72 62.17 90 bottom
C1401  33pF_50V  [CSC_100X050X040_2]  221.59 51.62 90 bottom
C1402  4.7pF_50V_1  [CSC_060X030X033_2]  211.2 61.61 0 bottom
C1403  18pF_50V_1  [CSC_060X030X030_2]  219.17 64.33 180 bottom
C1404  18pF_50V_1  [CSC_060X030X030_2]  219.17 63.69 180 bottom
C1405  18pF_50V_1  [CSC_060X030X030_2]  269.23 46.46 90 top
C1406  100pF_50V_1  [CSC_060X030X030_2]  214.53 56.71 270 top
C1407  82pF_50V_2  [CSC_100X050X040_2]  202.08 56.45 270 top
C1408  68pF_50V_2  [CSC_100X050X040_2]  217.45 62.17 90 bottom
C1409  0.1uF_10V_1  [CSC_060X030X030_2]  209.9 65.52 270 bottom
C1410  1uF_6.3V_2  [CSC_100X050X055_2]  215.8 64.96 0 bottom
C1411  100pF_50V_2  [CSC_100X050X040_2]  198.9 61.41 180 bottom
C1413  0.01UF_25V_1  [CSC_060X030X033_2]  213.89 56.71 270 top
C1414  0.1uF_6.3V_1  [CSC_060X030X030_2]  203.1 56.96 0 top
C1415  4.7uF_6.3V_3  [CSC_160X080X090_2]  200.94 57.34 270 top
C1451  0.1uF_6.3V_1  [CSC_060X030X030_2]  279.37 48.34 90 bottom
C1452  4.7uF_6.3V_3  [CSC_160X080X090_2]  281.1 49.07 180 bottom
C1453  18pF_50V_1  [CSC_060X030X030_2]  269.84 43.18 270 top
C1956  10uF_6.3V_3  [RANGERS-6010B0044902-001]  247.67 20.79 180 top
C2200  0.1uF_6.3V_1  [CSC_060X030X030_2]  235.02 5.42 270 top
C2201  4.7uF_6.3V_3  [CSC_160X080X090_2]  237.97 5.12 270 top
C2250  0.1uF_10V_1  [CSC_060X030X030_2]  223.8 99.38 0 top
C2251  2.2UF_6.3V_2  [CSC_100X050X055_2]  222.55 99.23 90 bottom
C2255  0.1uF_10V_1  [CSC_060X030X030_2]  222.45 105.86 180 bottom
C2256  1uF_6.3V_1  [CSC_060X030X035_2]  222.45 105.22 180 bottom
C2257  0.1uF_6.3V_1  [CSC_060X030X030_2]  221.26 104.59 180 bottom
C2258  4.7uF_6.3V_3  [CSC_160X080X090_2]  221.76 103.32 180 bottom
C2410  0.1uF_16V_2  [CSC_100X050X040_2]  260.96 21.22 180 top
C2411  1uF_6.3V_2  [CSC_100X050X055_2]  260.96 20.33 180 top
C2419  390pF_50V_2  [CSC_100X050X040_2]  266.34 27.62 270 bottom
C2420  390pF_50V_2  [CSC_100X050X040_2]  253.15 30.99 180 top
C2421  390pF_50V_2  [CSC_100X050X040_2]  253.15 32.01 180 top
C2422  390pF_50V_2  [CSC_100X050X040_2]  267.64 29.88 270 top
C2423  1uF_6.3V_2  [CSC_100X050X055_2]  248.18 23.05 90 top
C2424  0.1uF_16V_2  [CSC_100X050X040_2]  247.29 22.67 90 top
C2425  0.1uF_16V_2  [CSC_100X050X040_2]  249.63 22.39 270 top
C2427  1uF_6.3V_2  [CSC_100X050X055_2]  249.57 23.76 180 top
C2432  0.1uF_16V_2  [CSC_100X050X040_2]  261.16 32.7 270 top
C2500  10uF_6.3V_3  [RANGERS-6010B0044902-001]  78.51 33.97 0 bottom
C2501  1uF_6.3V_2  [CSC_100X050X055_2]  77.62 28.13 270 bottom
C2502  22uF_6.3V_3  [CLOONEY-6010B0219002-001]  79.27 28.26 0 bottom
C2503  10uF_6.3V_3  [CSC_160X080X095_2]  13.23 31.99 180 top
C2504  0.1uF_16V_2  [CSC_100X050X040_2]  28.52 29.07 0 top
C2505  0.1uF_16V_2  [CSC_100X050X040_2]  26.11 31.84 90 top
C2506  10uF_6.3V_3  [CSC_160X080X095_2]  13.23 33.21 180 top
C2507  10uF_6.3V_3  [CSC_160X080X095_2]  13.23 30.77 180 top
C2508  10uF_6.3V_3  [RANGERS-6010B0044902-001]  29.74 26.99 0 top
C2600  10uF_25V_3  [CSC_160X080X090_2]  269.53 95.77 270 top
C2601  1000pF_25V_1  [CSC_060X030X030_2]  269.11 97.46 0 top
C2602  0.1uF_25V_2  [CSC_100X050X040_2]  270.46 86.37 90 top
C2603  10uF_6.3V_3  [CSC_160X080X095_2]  265.2 95.47 180 top
C2604  10uF_6.3V_3  [CSC_160X080X095_2]  265.2 94.25 180 top
C2605  10uF_6.3V_3  [CSC_160X080X095_2]  265.2 93.03 180 top
C2606  0.1uF_16V_2  [CSC_100X050X040_2]  266.8 47.06 270 top
C2607  1uF_6.3V_2  [CSC_100X050X055_2]  267.69 47.06 270 top
C2608  1UF_25V_2  [CSC_100X050X055_2]  271.37 86.37 90 top
C2609  1UF_25V_2  [CSC_100X050X055_2]  258.35 40.43 0 top
C2610  0.1uF_25V_2  [CSC_100X050X040_2]  258.26 41.34 0 top
C2611  0.1uF_16V_2  [CSC_100X050X040_2]  269.36 99.18 0 top
C2612  10uF_6.3V_3  [CSC_160X080X095_2]  262.33 48.35 0 top
C2613  1000pF_25V_1  [CSC_060X030X030_2]  265.05 39.36 270 top
C2614  10uF_6.3V_3  [CSC_160X080X095_2]  263.55 47.13 0 top
C2615  10uF_6.3V_3  [CSC_160X080X095_2]  265.2 91.81 180 top
C2616  10uF_6.3V_3  [CSC_160X080X095_2]  265.2 90.59 180 top
C2617  1uF_6.3V_2  [CSC_100X050X055_2]  269.36 98.29 0 top
C2620  10uF_25V_3  [CSC_160X080X090_2]  263.47 38.52 180 top
C2630  10uF_6.3V_3  [CSC_160X080X095_2]  263.55 45.91 0 top
C2633  10uF_6.3V_3  [CSC_160X080X095_2]  263.55 44.69 0 top
C2634  10uF_6.3V_3  [CSC_160X080X095_2]  263.55 43.47 0 top
C2700  0.22uF_6.3V_1  [CSC_060X030X030_2]  253.72 56.05 270 top
C2701  0.22uF_6.3V_1  [CSC_060X030X030_2]  253.11 56.05 270 top
C2702  0.22uF_6.3V_1  [CSC_060X030X030_2]  256.16 56.05 270 top
C2703  0.22uF_6.3V_1  [CSC_060X030X030_2]  255.55 56.05 270 top
C2704  0.22uF_6.3V_1  [CSC_060X030X030_2]  258.59 56.05 270 top
C2705  0.22uF_6.3V_1  [CSC_060X030X030_2]  257.98 56.05 270 top
C2706  0.22uF_6.3V_1  [CSC_060X030X030_2]  261.06 56.05 270 top
C2707  0.22uF_6.3V_1  [CSC_060X030X030_2]  260.45 56.05 270 top
C2708  0.22uF_6.3V_1  [CSC_060X030X030_2]  268.79 71.32 90 top
C2709  0.22uF_6.3V_1  [CSC_060X030X030_2]  269.4 71.32 90 top
C2710  0.22uF_6.3V_1  [CSC_060X030X030_2]  268.83 73.23 90 top
C2711  0.22uF_6.3V_1  [CSC_060X030X030_2]  268.22 73.23 90 top
C2712  0.22uF_6.3V_1  [CSC_060X030X030_2]  267.59 73.8 90 top
C2713  0.22uF_6.3V_1  [CSC_060X030X030_2]  266.98 73.8 90 top
C2714  0.22uF_6.3V_1  [CSC_060X030X030_2]  266.26 73.8 90 top
C2715  0.22uF_6.3V_1  [CSC_060X030X030_2]  265.66 73.8 90 top
C2716  0.22uF_6.3V_1  [CSC_060X030X030_2]  255.7 71.95 90 top
C2717  0.22uF_6.3V_1  [CSC_060X030X030_2]  256.31 71.95 90 top
C2718  0.22uF_6.3V_1  [CSC_060X030X030_2]  250.06 65.83 180 top
C2719  0.22uF_6.3V_1  [CSC_060X030X030_2]  250.06 66.44 180 top
C2720  0.22uF_6.3V_1  [CSC_060X030X030_2]  250.06 64.48 180 top
C2721  0.22uF_6.3V_1  [CSC_060X030X030_2]  250.06 65.09 180 top
C2722  0.22uF_6.3V_1  [CSC_060X030X030_2]  250.06 63.74 180 top
C2723  0.22uF_6.3V_1  [CSC_060X030X030_2]  250.06 63.13 180 top
C2724  0.22uF_6.3V_1  [CSC_060X030X030_2]  250.06 61.79 180 top
C2725  0.22uF_6.3V_1  [CSC_060X030X030_2]  250.06 62.4 180 top
C2726  0.22uF_6.3V_1  [CSC_060X030X030_2]  256.92 71.95 90 top
C2727  0.22uF_6.3V_1  [CSC_060X030X030_2]  257.53 71.95 90 top
C2728  0.33uF_25V_1  [CSC_060X030X039_2]  277.59 76.51 180 bottom
C2729  0.33uF_25V_1  [CSC_060X030X039_2]  277.59 75.9 180 bottom
C2730  0.22uF_25V_1  [CSC_060X030X033_2]  277.29 75.9 180 top
C2731  0.22uF_25V_1  [CSC_060X030X033_2]  277.29 76.51 180 top
C2732  0.33uF_25V_1  [CSC_060X030X039_2]  277.29 81.64 180 top
C2733  0.33uF_25V_1  [CSC_060X030X039_2]  277.29 81.03 180 top
C2734  0.22uF_25V_1  [CSC_060X030X033_2]  277.59 81.64 180 bottom
C2735  0.22uF_25V_1  [CSC_060X030X033_2]  277.59 81.03 180 bottom
C2736  0.33uF_25V_1  [CSC_060X030X039_2]  275.79 62.63 180 bottom
C2737  0.33uF_25V_1  [CSC_060X030X039_2]  275.79 63.24 180 bottom
C2738  0.22uF_25V_1  [CSC_060X030X033_2]  276.55 62.63 180 top
C2739  0.22uF_25V_1  [CSC_060X030X033_2]  276.55 63.24 180 top
C2740  0.22uF_25V_1  [CSC_060X030X033_2]  275.18 67.68 180 bottom
C2741  0.22uF_25V_1  [CSC_060X030X033_2]  275.18 68.29 180 bottom
C2742  0.33uF_25V_1  [CSC_060X030X039_2]  275.19 68.29 180 top
C2743  0.33uF_25V_1  [CSC_060X030X039_2]  275.19 67.68 180 top
C2744  22pF_50V_2  [CSC_100X050X040_2]  264.54 54.55 270 bottom
C2745  22pF_50V_2  [CSC_100X050X040_2]  264.54 56.17 90 bottom
C2746  0.1uF_6.3V_1  [CSC_060X030X030_2]  249.22 73.6 180 top
C2747  0.1uF_16V_2  [CSC_100X050X040_2]  247.55 56.58 90 top
C2748  1uF_6.3V_1  [CSC_060X030X035_2]  270.26 72.16 270 top
C2749  1uF_6.3V_1  [CSC_060X030X035_2]  270.26 73.3 90 top
C2750  1uF_6.3V_1  [CSC_060X030X035_2]  263.88 75.25 180 top
C2751  1uF_6.3V_1  [CSC_060X030X035_2]  263.88 74.64 180 top
C2752  10uF_6.3V_2  [CSC_100X050X070_2]  263.87 76.94 180 top
C2753  10uF_6.3V_2  [CSC_100X050X070_2]  263.88 76.01 180 top
C2754  10uF_6.3V_2  [CSC_100X050X070_2]  263.88 78.75 180 top
C2755  10uF_6.3V_2  [CSC_100X050X070_2]  263.88 77.84 180 top
C2756  2.2UF_6.3V_1  [CSC_060X030X033_2]  258.54 65.98 270 bottom
C2757  2.2UF_6.3V_1  [CSC_060X030X033_2]  256.82 65.72 180 bottom
C2758  2.2UF_6.3V_1  [CSC_060X030X033_2]  256.05 71.57 180 bottom
C2759  2.2UF_6.3V_1  [CSC_060X030X033_2]  259.74 62.55 270 bottom
C2760  2.2UF_6.3V_1  [CSC_060X030X033_2]  256.05 72.2 180 bottom
C2761  2.2UF_6.3V_1  [CSC_060X030X033_2]  258.47 61.91 270 bottom
C2762  47UF_4V_3  [CSC_160X080X100_2]  261.08 83.66 90 top
C2763  47UF_4V_3  [CSC_160X080X100_2]  259.41 83.66 90 top
C2764  47UF_4V_3  [CSC_160X080X100_2]  256.69 80.08 90 top
C2765  2.2UF_6.3V_1  [CSC_060X030X033_2]  257.45 62.42 270 bottom
C2766  2.2UF_6.3V_1  [CSC_060X030X033_2]  259.99 70.42 270 bottom
C2767  2.2UF_6.3V_1  [CSC_060X030X033_2]  258.85 62.93 0 bottom
C2768  2.2UF_6.3V_1  [CSC_060X030X033_2]  260.37 57.72 0 bottom
C2769  2.2UF_6.3V_1  [CSC_060X030X033_2]  260.12 59.12 270 bottom
C2770  2.2UF_6.3V_1  [CSC_060X030X033_2]  257.32 57.72 180 bottom
C2771  2.2UF_6.3V_1  [CSC_060X030X033_2]  257.4 60.03 180 bottom
C2772  10uF_6.3V_3  [RANGERS-6010B0044902-001]  256.46 59.12 180 bottom
C2773  10uF_6.3V_2  [CSC_100X050X070_2]  271.52 75.22 90 top
C2774  10uF_6.3V_2  [CSC_100X050X070_2]  272.41 75.17 90 top
C2775  1uF_6.3V_1  [CSC_060X030X035_2]  270.59 75.27 90 top
C2776  1uF_6.3V_1  [CSC_060X030X035_2]  269.99 75.27 90 top
C2777  1uF_6.3V_1  [CSC_060X030X035_2]  253.08 63.26 90 bottom
C2778  1uF_6.3V_1  [CSC_060X030X035_2]  263.19 61.79 0 bottom
C2779  1uF_6.3V_1  [CSC_060X030X035_2]  263.19 59.96 0 bottom
C2780  1uF_6.3V_1  [CSC_060X030X035_2]  263.19 61.18 0 bottom
C2781  1uF_6.3V_1  [CSC_060X030X035_2]  271.73 73.93 0 top
C2782  2.2UF_6.3V_1  [CSC_060X030X033_2]  259.36 70.42 270 bottom
C2783  2.2UF_6.3V_1  [CSC_060X030X033_2]  261.13 62.55 270 bottom
C2784  2.2UF_6.3V_1  [CSC_060X030X033_2]  255.17 63.57 180 bottom
C2785  2.2UF_6.3V_1  [CSC_060X030X033_2]  259.15 65.47 90 bottom
C2786  2.2UF_6.3V_1  [CSC_060X030X033_2]  255.29 64.96 225 bottom
C2815  10UF_25V_5  [CSC_200X125X140_2]  282.13 80.02 0 bottom
C2900  10UF_25V_5  [CSC_200X125X140_2]  281.63 64.89 0 bottom
C3000  0.1uF_16V_2  [CSC_100X050X040_2]  23.14 13.15 180 bottom
C3001  1uF_6.3V_1  [CSC_060X030X035_2]  19.58 23.69 0 top
C3003  4.7uF_6.3V_3  [CSC_160X080X090_2]  52.8 7.08 180 bottom
C3006  1uF_6.3V_1  [CSC_060X030X035_2]  53.16 9.65 180 top
C3009  0.1uF_6.3V_1  [CSC_060X030X030_2]  34.57 18.96 180 bottom
C3010  0.1uF_6.3V_1  [CSC_060X030X030_2]  34.57 19.6 180 bottom
C3011  0.1uF_6.3V_1  [CSC_060X030X030_2]  41.83 28.72 180 bottom
C3012  0.1uF_6.3V_1  [CSC_060X030X030_2]  41.83 29.35 180 bottom
C3013  0.1uF_6.3V_1  [CSC_060X030X030_2]  41.83 30.14 180 bottom
C3014  0.1uF_6.3V_1  [CSC_060X030X030_2]  41.83 30.77 180 bottom
C3015  0.1uF_6.3V_1  [CSC_060X030X030_2]  41.83 31.59 180 bottom
C3016  0.1uF_6.3V_1  [CSC_060X030X030_2]  41.83 32.22 180 bottom
C3017  0.1uF_6.3V_1  [CSC_060X030X030_2]  41.83 32.98 180 bottom
C3018  0.1uF_6.3V_1  [CSC_060X030X030_2]  41.83 33.62 180 bottom
C3150  0.1uF_6.3V_1  [CSC_060X030X030_2]  273.45 94.81 180 bottom
C3151  1uF_6.3V_1  [CSC_060X030X035_2]  271.93 95.06 0 bottom
C3152  0.1uF_6.3V_1  [CSC_060X030X030_2]  273.45 94.17 180 bottom
C3302  0.1uF_16V_2  [CSC_100X050X040_2]  236.84 85.48 270 top
C3304  0.1uF_16V_2  [CSC_100X050X040_2]  240.05 96.6 270 top
C3305  0.1uF_16V_2  [CSC_100X050X040_2]  239.16 96.6 270 top
C3306  0.1uF_16V_2  [CSC_100X050X040_2]  231.08 95.33 0 top
C3307  0.1uF_16V_2  [CSC_100X050X040_2]  231.08 94.44 0 top
C3308  0.1uF_16V_2  [CSC_100X050X040_2]  232.71 93.63 0 top
C3309  0.1uF_16V_2  [CSC_100X050X040_2]  232.71 92.74 0 top
C3310  0.1uF_16V_2  [CSC_100X050X040_2]  234.43 91.44 315 top
C3311  0.1uF_16V_2  [CSC_100X050X040_2]  233.79 90.81 315 top
C3312  0.1uF_16V_2  [CSC_100X050X040_2]  234.68 84.56 90 top
C3313  0.1uF_16V_2  [CSC_100X050X040_2]  235.57 84.56 90 top
C3315  0.1uF_16V_2  [CSC_100X050X040_2]  236.52 95.67 180 top
C3316  0.1uF_16V_2  [CSC_100X050X040_2]  246.58 94.02 0 top
C3369  0.01uF_50V_2  [CSC_100X050X040_2]  234.72 95.8 90 top
C3375  0.01uF_50V_2  [CSC_100X050X040_2]  244.26 85.56 0 top
C3503  1uF_6.3V_1  [CSC_060X030X035_2]  226.74 61.03 180 top
C3504  0.1uF_6.3V_1  [CSC_060X030X030_2]  228.77 54.83 0 top
C3506  0.1uF_6.3V_1  [CSC_060X030X030_2]  222.7 61.25 90 top
C3540  0.1uF_6.3V_1  [CSC_060X030X030_2]  219.61 56.2 270 top
C3800  4.7UF_6.3V_2  [CSC_100X050X065_2]  203.73 78.55 270 bottom
C3801  1uF_6.3V_1  [CSC_060X030X035_2]  193.44 74.89 270 top
C3802  0.1uF_25V_1  [CSC_060X030X033_2]  203.6 79.69 180 bottom
C3803  4.7UF_6.3V_2  [CSC_100X050X065_2]  202.59 76.65 180 bottom
C3804  0.1uF_25V_1  [CSC_060X030X033_2]  204.24 76.52 180 bottom
C4100  1uF_6.3V_1  [CSC_060X030X035_2]  162.46 9.92 0 top
C4101  1uF_6.3V_1  [CSC_060X030X035_2]  162.46 8.7 0 top
C4102  1uF_6.3V_1  [CSC_060X030X035_2]  162.46 10.53 0 top
C4103  1uF_6.3V_1  [CSC_060X030X035_2]  162.46 9.31 0 top
C4104  0.1uF_10V_1  [CSC_060X030X030_2]  163.85 18.61 270 top
C4105  2.2UF_6.3V_2  [CSC_100X050X055_2]  163.09 18.35 270 top
C4107  22uF_6.3V_3  [CLOONEY-6010B0219002-001]  158.01 20.39 0 top
C4108  1uF_6.3V_1  [CSC_060X030X035_2]  119.28 14.42 0 top
C4109  22uF_6.3V_3  [CLOONEY-6010B0219002-001]  132.74 13.02 180 top
C4110  0.1uF_10V_1  [CSC_060X030X030_2]  139.98 12.77 270 top
C4111  2.2UF_6.3V_2  [CSC_100X050X055_2]  139.21 12.77 270 top
C4112  1uF_6.3V_1  [CSC_060X030X035_2]  113.56 13.53 90 top
C4113  22uF_6.3V_3  [CLOONEY-6010B0219002-001]  152.17 10.86 270 top
C4114  1uF_6.3V_1  [CSC_060X030X035_2]  115.85 13.53 90 top
C4115  2.2UF_6.3V_2  [CSC_100X050X055_2]  128.55 21.15 270 top
C4116  1uF_6.3V_1  [CSC_060X030X035_2]  119.78 20.26 180 top
C4117  22uF_6.3V_3  [CLOONEY-6010B0219002-001]  129.69 20.77 270 top
C4118  22uF_6.3V_3  [CLOONEY-6010B0219002-001]  137.31 20.89 270 top
C4119  0.1uF_10V_1  [CSC_060X030X030_2]  121.56 13.02 180 top
C4121  2.2UF_6.3V_2  [CSC_100X050X055_2]  97.05 23.18 90 top
C4122  0.022uF_6.3V_1  [CSC_060X030X030_2]  129.71 43.49 0 top
C4123  2.2UF_6.3V_2  [CSC_100X050X055_2]  124.23 22.54 270 top
C4124  0.022uF_6.3V_1  [CSC_060X030X030_2]  132.17 43.49 180 top
C4125  1uF_6.3V_1  [CSC_060X030X035_2]  240.94 14.42 90 top
C4126  1uF_6.3V_1  [CSC_060X030X035_2]  240.31 14.42 90 top
C4127  1uF_6.3V_1  [CSC_060X030X035_2]  242.21 14.42 90 top
C4128  1uF_6.3V_1  [CSC_060X030X035_2]  241.58 14.42 90 top
C4129  0.1uF_10V_1  [CSC_060X030X030_2]  235.99 22.29 180 top
C4130  2.2UF_6.3V_2  [CSC_100X050X055_2]  235.86 21.53 180 top
C4131  2.2UF_6.3V_2  [CSC_100X050X055_2]  128.93 14.92 90 top
C4132  22uF_6.3V_3  [CLOONEY-6010B0219002-001]  212.11 12.51 270 top
C4133  22uF_6.3V_3  [CLOONEY-6010B0219002-001]  197.89 21.27 180 top
C4134  2.2UF_6.3V_2  [CSC_100X050X055_2]  203.1 12.51 270 top
C4135  0.1uF_10V_1  [CSC_060X030X030_2]  215.03 22.42 270 top
C4136  0.1uF_10V_1  [CSC_060X030X030_2]  203.6 14.8 270 top
C4137  2.2UF_6.3V_2  [CSC_100X050X055_2]  132.61 21.66 180 top
C4138  2.2UF_6.3V_2  [CSC_100X050X055_2]  189.91 18.94 270 top
C4139  0.1uF_10V_1  [CSC_060X030X030_2]  223.29 21.53 0 top
C4140  22uF_6.3V_3  [CLOONEY-6010B0219002-001]  178.71 20.77 90 top
C4141  22uF_6.3V_3  [CLOONEY-6010B0219002-001]  194.84 12.77 0 top
C4142  0.1uF_10V_1  [CSC_060X030X030_2]  233.19 21.53 0 top
C4143  22uF_6.3V_3  [CLOONEY-6010B0219002-001]  212.95 20.19 270 top
C4144  0.1uF_10V_1  [CSC_060X030X030_2]  215.8 12.13 90 top
C4145  2.2UF_6.3V_2  [CSC_100X050X055_2]  215.03 12.38 90 top
C4146  2.2UF_6.3V_2  [CSC_100X050X055_2]  130.53 12.89 0 top
C4147  2.2UF_6.3V_2  [CSC_100X050X055_2]  228.37 13.02 0 top
C4148  2.2UF_6.3V_2  [CSC_100X050X055_2]  184.43 12.89 0 top
C4149  2.2UF_6.3V_2  [CSC_100X050X055_2]  173.89 13.02 0 top
C4150  2.2UF_6.3V_2  [CSC_100X050X055_2]  206.91 14.04 90 top
C4151  2.2UF_6.3V_2  [CSC_100X050X055_2]  135.53 14.54 0 top
C4152  2.2UF_6.3V_2  [CSC_100X050X055_2]  205.89 21.02 270 top
C4350  1uF_6.3V_1  [CSC_060X030X035_2]  219.73 5.27 180 top
C4351  0.1uF_10V_1  [CSC_060X030X030_2]  229.13 7.3 0 top
C4411  0.1uF_10V_1  [CSC_060X030X030_2]  117.5 84.65 180 bottom
C4412  1000pF_25V_1  [CSC_060X030X030_2]  117.75 85.79 90 bottom
C4413  0.1uF_10V_1  [CSC_060X030X030_2]  103.15 108.78 270 bottom
C4500  0.1uF_6.3V_1  [CSC_060X030X030_2]  146.83 55.43 90 top
C4501  0.1uF_6.3V_1  [CSC_060X030X030_2]  150.52 55.43 90 top
C4502  10uF_6.3V_3  [RANGERS-6010B0044902-001]  161.15 55.37 0 top
C4503  10uF_6.3V_3  [RANGERS-6010B0044902-001]  158.79 55.36 0 top
C4504  1uF_6.3V_1  [CSC_060X030X035_2]  187.02 63.82 270 top
C4505  0.1uF_6.3V_1  [CSC_060X030X030_2]  149.37 55.43 90 top
C4506  0.1uF_10V_1  [CSC_060X030X030_2]  144.74 55.55 180 top
C4507  10uF_6.3V_3  [RANGERS-6010B0044902-001]  156.34 55.35 0 top
C4508  10uF_6.3V_3  [RANGERS-6010B0044902-001]  152.11 55.34 180 top
C4509  22uF_6.3V_3  [CLOONEY-6010B0219002-001]  162.18 58.4 90 top
C4510  22uF_6.3V_3  [CLOONEY-6010B0219002-001]  164.2 55.37 0 top
C4511  22uF_6.3V_3  [CLOONEY-6010B0219002-001]  154.94 58.4 90 top
C4512  1uF_6.3V_1  [CSC_060X030X035_2]  163.62 76.89 90 top
C4513  22uF_6.3V_3  [CLOONEY-6010B0219002-001]  173.35 70.55 180 top
C4514  47pF_50V_1  [CSC_060X030X030_2]  142.41 85.52 0 bottom
C4515  1uF_6.3V_1  [CSC_060X030X035_2]  166.61 55.06 180 top
C4516  0.1uF_6.3V_1  [CSC_060X030X030_2]  166.34 75.47 0 top
C4517  1uF_6.3V_1  [CSC_060X030X035_2]  183.18 84.64 90 bottom
C4518  1uF_6.3V_1  [CSC_060X030X035_2]  170.84 75.86 90 top
C4519  1uF_6.3V_1  [CSC_060X030X035_2]  174.06 71.46 180 top
C4520  0.1uF_10V_1  [CSC_060X030X030_2]  166.99 61.42 270 top
C4521  1uF_6.3V_1  [CSC_060X030X035_2]  166.93 66.33 180 top
C4522  22uF_6.3V_3  [CLOONEY-6010B0219002-001]  164.46 68.76 180 top
C4523  22uF_6.3V_3  [CLOONEY-6010B0219002-001]  172.74 66.36 180 top
C4524  0.1uF_10V_1  [CSC_060X030X030_2]  169.97 62.41 0 top
C4525  1uF_6.3V_1  [CSC_060X030X035_2]  153.03 63.92 180 top
C4526  1uF_6.3V_1  [CSC_060X030X035_2]  152.5 62.01 180 top
C4527  1uF_6.3V_1  [CSC_060X030X035_2]  164.36 61.98 180 top
C4528  22uF_6.3V_3  [CLOONEY-6010B0219002-001]  164.46 67.54 180 top
C4529  2.2UF_6.3V_2  [CSC_100X050X055_2]  162.07 89.09 180 top
C4530  0.1uF_10V_1  [CSC_060X030X030_2]  187.63 63.82 270 top
C4531  1uF_6.3V_1  [CSC_060X030X035_2]  168.75 63.25 0 top
C4532  4.7UF_6.3V_2  [CSC_100X050X065_2]  166.98 73.04 270 top
C4533  22uF_6.3V_3  [CLOONEY-6010B0219002-001]  172.87 77.05 270 top
C4534  1uF_6.3V_1  [CSC_060X030X035_2]  168.75 61.58 0 top
C4535  0.1uF_10V_1  [CSC_060X030X030_2]  170.32 65.32 0 top
C4536  1uF_6.3V_1  [CSC_060X030X035_2]  170.41 66.53 0 top
C4538  1uF_6.3V_1  [CSC_060X030X035_2]  174.67 68.76 270 top
C4539  1uF_6.3V_1  [CSC_060X030X035_2]  174.77 67.12 270 top
C4540  22uF_6.3V_3  [CLOONEY-6010B0219002-001]  167.54 65.41 0 top
C4541  1uF_6.3V_1  [CSC_060X030X035_2]  167.61 64.16 90 top
C4542  0.1uF_10V_1  [CSC_060X030X030_2]  167 64.16 90 top
C4543  4.7UF_6.3V_2  [CSC_100X050X065_2]  173.66 72.58 270 top
C4544  4.7uF_10V_3  [CSC_160X080X080_2]  189.27 62.66 0 bottom
C4545  1uF_6.3V_1  [CSC_060X030X035_2]  174.22 65.42 270 top
C4546  0.1uF_10V_1  [CSC_060X030X030_2]  173.55 64.76 270 top
C4547  1uF_6.3V_1  [CSC_060X030X035_2]  170.84 78.19 180 top
C4548  1uF_6.3V_1  [CSC_060X030X035_2]  174.82 69.9 90 top
C4549  1uF_6.3V_1  [CSC_060X030X035_2]  169.97 61.77 0 top
C4550  1uF_6.3V_1  [CSC_060X030X035_2]  162.69 72.16 90 top
C4551  1uF_6.3V_1  [CSC_060X030X035_2]  161.77 61.81 180 top
C4552  1uF_6.3V_1  [CSC_060X030X035_2]  163.08 61.55 90 top
C4553  22uF_6.3V_3  [CLOONEY-6010B0219002-001]  142.06 68.92 270 top
C4554  1uF_6.3V_1  [CSC_060X030X035_2]  163.93 61.38 0 top
C4555  1uF_6.3V_1  [CSC_060X030X035_2]  161.11 62.9 180 top
C4556  22uF_6.3V_3  [CSC_160X080X100_2]  121.79 90.39 225 bottom
C4557  22uF_6.3V_3  [CLOONEY-6010B0219002-001]  157.22 66.33 0 top
C4558  1uF_6.3V_1  [CSC_060X030X035_2]  160.91 61.58 90 top
C4559  1uF_6.3V_1  [CSC_060X030X035_2]  156.21 72.15 90 top
C4560  1uF_6.3V_1  [CSC_060X030X035_2]  161.87 73.06 270 top
C4561  1uF_6.3V_1  [CSC_060X030X035_2]  160.53 73.26 90 top
C4562  1uF_6.3V_1  [CSC_060X030X035_2]  160.53 74.81 270 top
C4563  1uF_6.3V_1  [CSC_060X030X035_2]  161.87 71.94 90 top
C4564  1uF_6.3V_1  [CSC_060X030X035_2]  161.06 77.15 90 top
C4565  1uF_6.3V_1  [CSC_060X030X035_2]  160.04 71.7 270 top
C4566  22uF_6.3V_3  [CLOONEY-6010B0219002-001]  146.94 66.5 90 top
C4567  22uF_6.3V_3  [CLOONEY-6010B0219002-001]  140.84 66.5 90 top
C4568  22uF_6.3V_3  [CLOONEY-6010B0219002-001]  138.88 65.14 180 top
C4569  22uF_6.3V_3  [CLOONEY-6010B0219002-001]  159.64 69.98 180 top
C4570  10uF_6.3V_3  [RANGERS-6010B0044902-001]  159.64 68.76 180 top
C4571  10uF_6.3V_3  [RANGERS-6010B0044902-001]  162 68.76 0 top
C4572  22uF_6.3V_3  [CLOONEY-6010B0219002-001]  162 66.33 0 top
C4573  22uF_6.3V_3  [CLOONEY-6010B0219002-001]  159.64 63.89 180 top
C4574  22uF_6.3V_3  [CLOONEY-6010B0219002-001]  157.22 67.54 0 top
C4575  22uF_6.3V_3  [CLOONEY-6010B0219002-001]  162 69.98 0 top
C4576  22uF_6.3V_3  [CLOONEY-6010B0219002-001]  154.78 67.54 180 top
C4577  22uF_6.3V_3  [CLOONEY-6010B0219002-001]  164.46 63.89 180 top
C4578  22uF_6.3V_3  [CLOONEY-6010B0219002-001]  154.78 65.1 180 top
C4579  22uF_6.3V_3  [CLOONEY-6010B0219002-001]  159.64 67.54 180 top
C4580  22uF_6.3V_3  [CLOONEY-6010B0219002-001]  157.22 69.98 0 top
C4581  22uF_6.3V_3  [CLOONEY-6010B0219002-001]  157.22 68.76 0 top
C4582  22uF_6.3V_3  [CLOONEY-6010B0219002-001]  162 65.11 0 top
C4583  22uF_6.3V_3  [CLOONEY-6010B0219002-001]  157.22 63.89 0 top
C4584  22uF_6.3V_3  [CLOONEY-6010B0219002-001]  159.64 65.11 180 top
C4585  22uF_6.3V_3  [CLOONEY-6010B0219002-001]  164.46 66.33 180 top
C4586  22uF_6.3V_3  [CLOONEY-6010B0219002-001]  164.46 65.11 180 top
C4587  22uF_6.3V_3  [CLOONEY-6010B0219002-001]  164.46 69.98 180 top
C4588  1uF_6.3V_1  [CSC_060X030X035_2]  158.93 72.11 90 top
C4589  1uF_6.3V_1  [CSC_060X030X035_2]  163.01 76.67 270 top
C4590  1uF_6.3V_1  [CSC_060X030X035_2]  154.45 76.49 180 top
C4591  22uF_6.3V_3  [CSC_160X080X100_2]  120.62 91.56 225 bottom
C4592  22uF_6.3V_3  [CSC_160X080X100_2]  122.96 89.22 225 bottom
C4593  22uF_6.3V_3  [CLOONEY-6010B0219002-001]  157.22 65.11 0 top
C4594  22uF_6.3V_3  [CLOONEY-6010B0219002-001]  162 67.54 0 top
C4595  22uF_6.3V_3  [CLOONEY-6010B0219002-001]  159.64 66.33 180 top
C4596  22uF_6.3V_3  [CLOONEY-6010B0219002-001]  154.78 66.32 180 top
C4597  22uF_6.3V_3  [CLOONEY-6010B0219002-001]  149.26 66.85 0 top
C4598  22uF_6.3V_3  [CLOONEY-6010B0219002-001]  142.15 64.15 270 top
C4599  22uF_6.3V_3  [CLOONEY-6010B0219002-001]  142.06 66.5 90 top
C4600  22uF_6.3V_3  [CLOONEY-6010B0219002-001]  149.04 63.9 0 top
C4601  22uF_6.3V_3  [CLOONEY-6010B0219002-001]  143.37 64.15 270 top
C4602  1uF_6.3V_1  [CSC_060X030X035_2]  140.66 76.8 0 top
C4603  1uF_6.3V_1  [CSC_060X030X035_2]  141.65 77.65 270 top
C4604  1uF_6.3V_1  [CSC_060X030X035_2]  138.99 76.59 180 top
C4605  1uF_6.3V_1  [CSC_060X030X035_2]  138.99 77.2 180 top
C4606  1uF_6.3V_1  [CSC_060X030X035_2]  141.01 77.65 270 top
C4607  22uF_6.3V_3  [CLOONEY-6010B0219002-001]  143.28 66.5 90 top
